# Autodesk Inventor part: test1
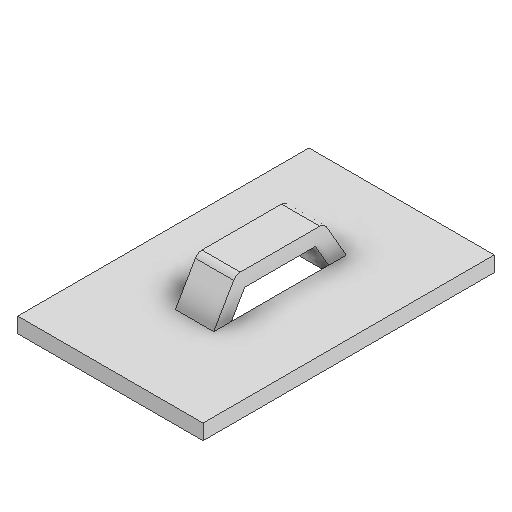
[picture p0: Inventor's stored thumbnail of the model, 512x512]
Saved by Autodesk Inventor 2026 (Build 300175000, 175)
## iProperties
Created: 2025-08
Part Number: test1
Material: Generic
Document SubType Name: Sheet Metal
Designer: sup1
Density: 1 g/cm^3
Sheet Metal Rule: Default
Appearance: Default
Author: sup1
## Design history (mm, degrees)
node "Face1"
  sketch "Sketch1"
    geometry: L1 (12.094, 18.532)-(-12.094, 18.532); L2 (-12.094, 18.532)-(-12.094, -19.478); L3 (-12.094, -19.478)-(12.094, -19.478); L4 (12.094, -19.478)-(12.094, 18.532)
    constraints: 8 end point, 2 parallel, 1 horizontal, 1 perpendicular
sketch "Sketch2"
  geometry: L1 (2.46, 8.65)-(-2.54, 8.65); L2 (-2.54, 8.65)-(-2.54, -6.35); L3 (-2.54, -6.35)-(2.46, -6.35); L4 (2.46, -6.35)-(2.46, 8.65); L5 (2.46, 8.65)-(-2.54, -6.35); L6 (-2.54, 8.65)-(2.46, -6.35); 1 further point
  constraints: 12 end point, 2 parallel, 1 horizontal, 1 midpoint, 1 perpendicular
  dimensions: "Length" = 15 distance of L1.end L2.end; "Width" = 5 distance of L2.end L3.end
extrude "Extrusion1" cut sketch "Sketch2" distance "d3" = 2 (= Thickness); taper "d4" = 0 deg
workplane "Work Plane2"
sketch "Sketch3"
  geometry: L1 (1.732, 5)-(13.268, 5); L2 (13.268, 5)-(16.732, -1); L3 (16.732, -1)-(15, -2); L4 (15, -2)-(12.113, 3); L5 (12.113, 3)-(2.887, 3); L6 (2.887, 3)-(0, -2); L7 (0, -2)-(-1.732, -1); L8 (-1.732, -1)-(1.732, 5); L9 (15, 0)-(0, 0) reference; L10 (0, 0)-(15, 0) reference; 1 further point
  constraints: 16 end point, 3 parallel, 2 perpendicular, 1 horizontal, 1 midpoint
  dimensions: "Angle" = 60 deg angle of L6 L9; "d14" = 2 vertical distance of L6.end point (7.5, 0) (= Thickness); "d15" = 2 vertical distance of L3.end point (7.5, 0) (= Thickness); "d16" = 5 distance from line of L1 point (7.5, 0) (= Height); "d17" = 3 distance from line of L5 point (7.5, 0) (= Height - Thickness); "d18" = 7.5 horizontal distance of L3.end point (7.5, 0) (= 0.5 x Length); "d19" = 60 deg angle of L4 L9 (= Angle); "d20" = 7.5 horizontal distance of L6.end point (7.5, 0) (= 0.5 x Length); "d21" = 2 distance between parallel lines of L8 L6 (= Thickness); "d22" = 2 distance between parallel lines of L4 L2 (= Thickness)
extrude "Extrusion2" join sketch "Sketch3" stored distance "d12" = 5 (= Width); taper "d13" = 0 deg
fillet "Fillet1" dims "d23" = 1 (= 0.5 x Thickness)
body "Solid1"
face "Plate1" dims "d0" = 2 (= Thickness)
other parameters: "Thickness" = 2 (derived), "BendRadius" = 2 (= Thickness), "BendReliefWidth" = 2 (= Thickness), "BendReliefDepth" = 1 (= 0.5 x Thickness), "CornerReliefSize" = 8 (= 4 x Thickness), "SeamGap" = 0.00508, "MinimumRemnant" = 4 (= 2 x Thickness), "TransitionRadius" = 2 (= BendRadius), "JacobiRadiusSize" = 2 (= BendRadius), "GapSize" = 2 (= Thickness), "Height" = 5 [user parameter; used in 2 equation terms]
